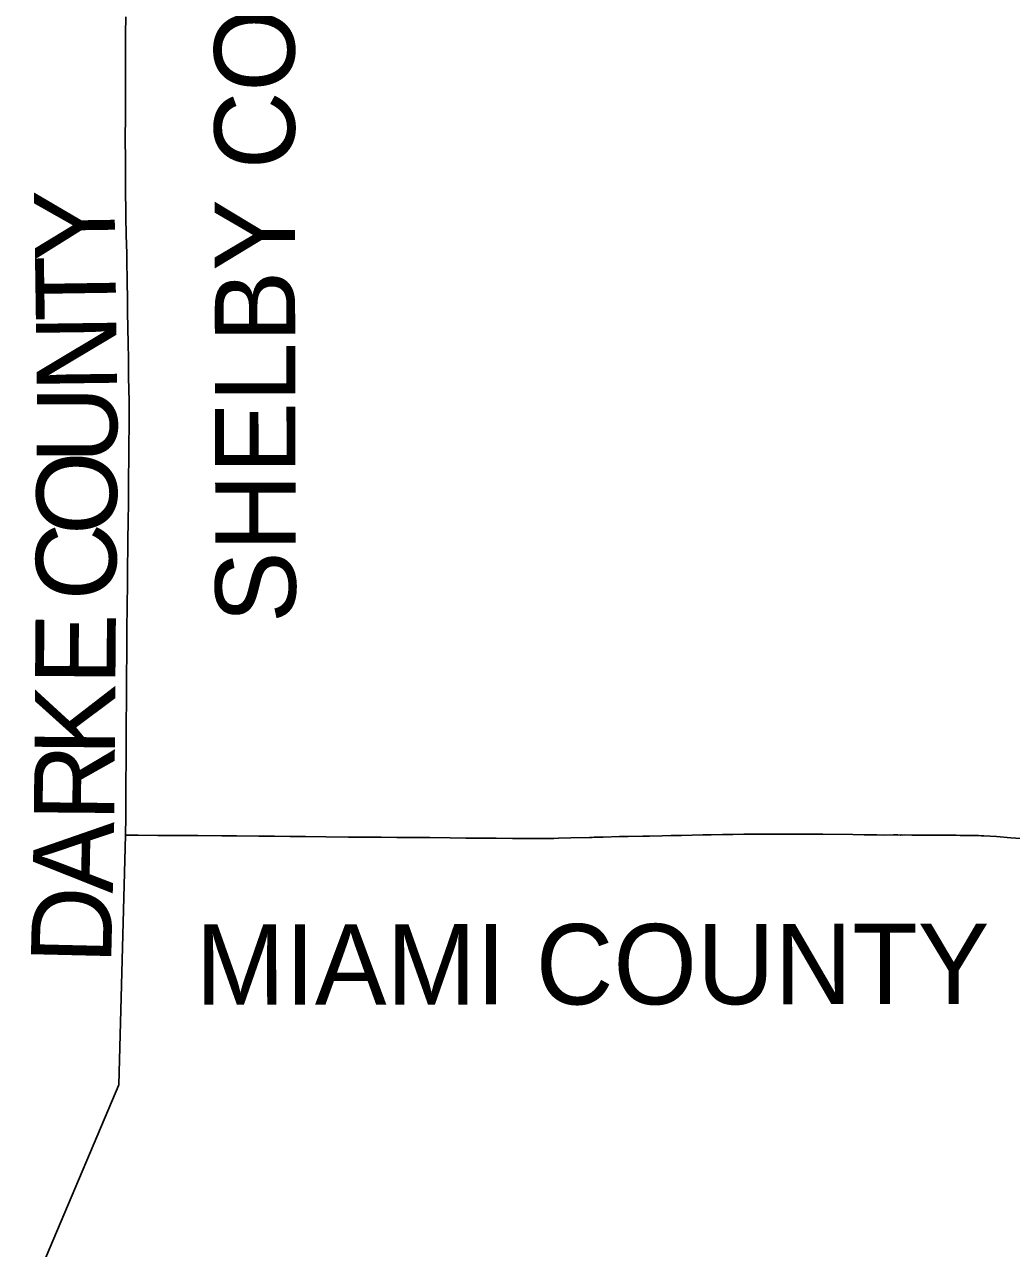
# Model space of a CAD drawing. Extents: x 0 to 34, y 0 to 22.
# Drawn here: x 4.2472 to 4.4446, y 17.6689 to 17.9138 of the extents above; entities that cross this region are included whole.
import ezdxf

# ---------------------------------------------------------------- set-up
doc = ezdxf.new("R2010")
doc.units = 0
doc.layers.add('GM_X_County', color=7, linetype='Continuous')
doc.layers.add('GM_X_County_Text', color=7, linetype='Continuous')

msp = doc.modelspace()

# ---------------------------------------------------------------- linework, layer by layer
at = {"layer": 'GM_X_County'}
for points in [[(4.267452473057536, 17.915329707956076), (4.267428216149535, 17.91190238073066), (4.267434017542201, 17.907208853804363), (4.267425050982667, 17.90367499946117), (4.2674208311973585, 17.90019493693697), (4.267419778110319, 17.898137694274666), (4.2673939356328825, 17.8954486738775), (4.267370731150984, 17.890966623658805), (4.267396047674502, 17.88664225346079), (4.267389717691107, 17.883953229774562), (4.267434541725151, 17.87925970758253), (4.267442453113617, 17.87751994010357), (4.267506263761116, 17.87435682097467), (4.267535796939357, 17.87256431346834), (4.267556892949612, 17.871510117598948), (4.267595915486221, 17.869982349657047), (4.267660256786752, 17.86776690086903), (4.267675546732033, 17.86660670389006), (4.26768715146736, 17.865190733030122), (4.267716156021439, 17.86372361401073), (4.267744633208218, 17.86187784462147), (4.267779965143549, 17.859293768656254), (4.267803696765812, 17.857817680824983), (4.267830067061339, 17.856446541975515), (4.267866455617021, 17.852914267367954), (4.267929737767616, 17.850173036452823), (4.2679930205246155, 17.846692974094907), (4.268041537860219, 17.84316017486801), (4.268120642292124, 17.838414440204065), (4.268126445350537, 17.837349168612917), (4.268130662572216, 17.83651488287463), (4.268118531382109, 17.83456364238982), (4.26811326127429, 17.833034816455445), (4.268107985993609, 17.830239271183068), (4.268076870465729, 17.826547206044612), (4.26803257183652, 17.823489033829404), (4.267976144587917, 17.81853182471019), (4.267916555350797, 17.813891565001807), (4.2678843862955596, 17.811149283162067), (4.267845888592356, 17.808670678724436), (4.267789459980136, 17.805613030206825), (4.2677773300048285, 17.801869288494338), (4.267734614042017, 17.797439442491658), (4.2676987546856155, 17.79264044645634), (4.26765867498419, 17.788211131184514), (4.267622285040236, 17.783253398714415), (4.267595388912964, 17.780775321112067), (4.267544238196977, 17.771757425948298), (4.267514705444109, 17.767749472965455), (4.267482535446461, 17.76089428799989), (4.267474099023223, 17.758204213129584), (4.2674530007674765, 17.755251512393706), (4.267427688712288, 17.75160902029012), (4.266090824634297, 17.701618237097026), (4.247204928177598, 17.65706455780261)], [(4.449619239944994, 17.750726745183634), (4.444516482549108, 17.7510885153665), (4.4416254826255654, 17.751307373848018), (4.439100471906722, 17.75146241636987), (4.438539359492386, 17.75148298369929), (4.438047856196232, 17.751500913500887), (4.436942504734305, 17.751507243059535), (4.436678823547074, 17.75151567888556), (4.436098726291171, 17.751522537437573), (4.434357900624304, 17.751543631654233), (4.433567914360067, 17.751566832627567), (4.432671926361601, 17.75156946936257), (4.431828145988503, 17.751581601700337), (4.431038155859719, 17.751600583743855), (4.427400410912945, 17.751621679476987), (4.4267681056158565, 17.751616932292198), (4.425660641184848, 17.751622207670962), (4.424711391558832, 17.751623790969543), (4.423183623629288, 17.751635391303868), (4.422869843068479, 17.751618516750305), (4.422553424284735, 17.75162642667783), (4.422343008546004, 17.751616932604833), (4.421869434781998, 17.75164171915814), (4.421027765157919, 17.75164910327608), (4.419024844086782, 17.751619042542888), (4.417704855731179, 17.75162589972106), (4.415175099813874, 17.75167599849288), (4.412855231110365, 17.75169340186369), (4.406897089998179, 17.751783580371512), (4.401361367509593, 17.75180625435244), (4.399832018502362, 17.751788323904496), (4.397563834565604, 17.751815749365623), (4.395139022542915, 17.75181785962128), (4.392397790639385, 17.7517888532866), (4.391079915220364, 17.75176881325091), (4.388865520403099, 17.751733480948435), (4.3868082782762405, 17.75170341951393), (4.384541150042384, 17.75168179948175), (4.382854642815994, 17.75165226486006), (4.378637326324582, 17.751554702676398), (4.37652735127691, 17.751521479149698), (4.374735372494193, 17.751489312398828), (4.37220456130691, 17.751422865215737), (4.370886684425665, 17.75140756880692), (4.367935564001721, 17.751330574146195), (4.366194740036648, 17.751295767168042), (4.362927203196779, 17.75122299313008), (4.361717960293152, 17.75117658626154), (4.361562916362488, 17.75115970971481), (4.361143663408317, 17.751161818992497), (4.360724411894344, 17.751144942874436), (4.3606205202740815, 17.751135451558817), (4.3602002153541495, 17.75114599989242), (4.356511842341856, 17.75105529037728), (4.354035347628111, 17.75098989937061), (4.353086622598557, 17.750954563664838), (4.352861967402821, 17.750950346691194), (4.352083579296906, 17.75093610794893), (4.350342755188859, 17.75093716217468), (4.349129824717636, 17.75093452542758), (4.344804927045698, 17.750954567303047), (4.341536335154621, 17.75099148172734), (4.3383194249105, 17.75100255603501), (4.335472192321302, 17.751018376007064), (4.332360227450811, 17.751040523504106), (4.328247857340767, 17.751092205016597), (4.3235543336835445, 17.751110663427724), (4.3217080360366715, 17.751130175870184), (4.318544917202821, 17.751191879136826), (4.3154345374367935, 17.751212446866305), (4.312006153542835, 17.75122457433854), (4.307471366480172, 17.75126518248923), (4.303411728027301, 17.75130842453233), (4.300351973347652, 17.751312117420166), (4.297188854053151, 17.751360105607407), (4.294077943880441, 17.751386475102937), (4.289595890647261, 17.751434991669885), (4.286695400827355, 17.751448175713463), (4.281844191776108, 17.751508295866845), (4.279417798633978, 17.751534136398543), (4.2781004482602, 17.751553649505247), (4.273882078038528, 17.751552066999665), (4.269926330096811, 17.75158159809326), (4.267427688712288, 17.75160902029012), (4.2674530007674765, 17.755251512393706), (4.267474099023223, 17.758204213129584), (4.267482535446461, 17.76089428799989), (4.267514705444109, 17.767749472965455), (4.267544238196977, 17.771757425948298), (4.267595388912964, 17.780775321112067), (4.267622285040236, 17.783253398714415), (4.26765867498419, 17.788211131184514), (4.2676987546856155, 17.79264044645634), (4.267734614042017, 17.797439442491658), (4.2677773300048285, 17.801869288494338), (4.267789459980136, 17.805613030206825), (4.267845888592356, 17.808670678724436), (4.2678843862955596, 17.811149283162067), (4.267916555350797, 17.813891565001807), (4.267976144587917, 17.81853182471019), (4.26803257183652, 17.823489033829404), (4.268076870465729, 17.826547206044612), (4.268107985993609, 17.830239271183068), (4.26811326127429, 17.833034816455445), (4.268118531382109, 17.83456364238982), (4.268130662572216, 17.83651488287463), (4.268126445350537, 17.837349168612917), (4.268120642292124, 17.838414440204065), (4.268041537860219, 17.84316017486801), (4.2679930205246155, 17.846692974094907), (4.267929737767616, 17.850173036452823), (4.267866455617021, 17.852914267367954), (4.267830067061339, 17.856446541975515), (4.267803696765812, 17.857817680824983), (4.267779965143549, 17.859293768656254), (4.267744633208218, 17.86187784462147), (4.267716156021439, 17.86372361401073), (4.26768715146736, 17.865190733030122), (4.267675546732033, 17.86660670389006), (4.267660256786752, 17.86776690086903), (4.267595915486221, 17.869982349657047), (4.267556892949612, 17.871510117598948), (4.267535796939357, 17.87256431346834), (4.267506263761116, 17.87435682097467), (4.267442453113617, 17.87751994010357), (4.267434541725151, 17.87925970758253), (4.267389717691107, 17.883953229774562), (4.267396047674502, 17.88664225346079), (4.267370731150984, 17.890966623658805), (4.2673939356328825, 17.8954486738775), (4.267419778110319, 17.898137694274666), (4.2674208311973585, 17.90019493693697), (4.267425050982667, 17.90367499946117), (4.267434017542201, 17.907208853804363), (4.267428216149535, 17.91190238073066), (4.267452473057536, 17.915329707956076)], [(4.247204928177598, 17.65706455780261), (4.266090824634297, 17.701618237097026), (4.267427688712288, 17.75160902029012), (4.269926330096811, 17.75158159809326), (4.273882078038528, 17.751552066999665), (4.2781004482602, 17.751553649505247), (4.279417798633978, 17.751534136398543), (4.281844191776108, 17.751508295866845), (4.286695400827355, 17.751448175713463), (4.289595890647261, 17.751434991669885), (4.294077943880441, 17.751386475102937), (4.297188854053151, 17.751360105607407), (4.300351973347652, 17.751312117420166), (4.303411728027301, 17.75130842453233), (4.307471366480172, 17.75126518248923), (4.312006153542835, 17.75122457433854), (4.3154345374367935, 17.751212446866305), (4.318544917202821, 17.751191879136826), (4.3217080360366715, 17.751130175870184), (4.3235543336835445, 17.751110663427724), (4.328247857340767, 17.751092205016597), (4.332360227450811, 17.751040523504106), (4.335472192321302, 17.751018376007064), (4.3383194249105, 17.75100255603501), (4.341536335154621, 17.75099148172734), (4.344804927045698, 17.750954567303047), (4.349129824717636, 17.75093452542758), (4.350342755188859, 17.75093716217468), (4.352083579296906, 17.75093610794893), (4.352861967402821, 17.750950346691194), (4.353086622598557, 17.750954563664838), (4.354035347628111, 17.75098989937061), (4.356511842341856, 17.75105529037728), (4.3602002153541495, 17.75114599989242), (4.3606205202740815, 17.751135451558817), (4.360724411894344, 17.751144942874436), (4.361143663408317, 17.751161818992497), (4.361562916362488, 17.75115970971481), (4.361717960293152, 17.75117658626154), (4.362927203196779, 17.75122299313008), (4.366194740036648, 17.751295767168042), (4.367935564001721, 17.751330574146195), (4.370886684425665, 17.75140756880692), (4.37220456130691, 17.751422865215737), (4.374735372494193, 17.751489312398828), (4.37652735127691, 17.751521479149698), (4.378637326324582, 17.751554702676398), (4.382854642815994, 17.75165226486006), (4.384541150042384, 17.75168179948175), (4.3868082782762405, 17.75170341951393), (4.388865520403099, 17.751733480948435), (4.391079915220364, 17.75176881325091), (4.392397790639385, 17.7517888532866), (4.395139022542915, 17.75181785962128), (4.397563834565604, 17.751815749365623), (4.399832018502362, 17.751788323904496), (4.401361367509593, 17.75180625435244), (4.406897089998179, 17.751783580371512), (4.412855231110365, 17.75169340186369), (4.415175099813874, 17.75167599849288), (4.417704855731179, 17.75162589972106), (4.419024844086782, 17.751619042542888), (4.421027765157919, 17.75164910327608), (4.421869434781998, 17.75164171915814), (4.422343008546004, 17.751616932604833), (4.422553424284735, 17.75162642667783), (4.422869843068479, 17.751618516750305), (4.423183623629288, 17.751635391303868), (4.424711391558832, 17.751623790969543), (4.425660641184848, 17.751622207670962), (4.4267681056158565, 17.751616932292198), (4.427400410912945, 17.751621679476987), (4.431038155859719, 17.751600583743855), (4.431828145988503, 17.751581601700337), (4.432671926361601, 17.75156946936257), (4.433567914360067, 17.751566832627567), (4.434357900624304, 17.751543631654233), (4.436098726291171, 17.751522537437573), (4.436678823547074, 17.75151567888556), (4.436942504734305, 17.751507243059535), (4.438047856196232, 17.751500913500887), (4.438539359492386, 17.75148298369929), (4.439100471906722, 17.75146241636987), (4.4416254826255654, 17.751307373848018), (4.444516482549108, 17.7510885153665), (4.449619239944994, 17.750726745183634)]]:
    msp.add_lwpolyline(points, dxfattribs=at)

# ---------------------------------------------------------------- texts
at = {"layer": 'GM_X_County_Text'}
for s, height, rotation, p in [('SHELBY COUNTY', 0.016074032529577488, 90.122917, (4.301477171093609, 17.794024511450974)), ('Y', 0.016074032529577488, 90.854012, (4.265387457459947, 17.866547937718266)), ('T', 0.016074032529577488, 90.854012, (4.265566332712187, 17.854548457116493)), ('N', 0.016074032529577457, 90.781677, (4.265760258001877, 17.840339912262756)), ('U', 0.016074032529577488, 89.885521, (4.2657335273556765, 17.82587763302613)), ('O', 0.016074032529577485, 89.54287, (4.265619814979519, 17.811585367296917)), ('C', 0.016074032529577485, 89.542633, (4.26551526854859, 17.798482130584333)), ('E', 0.016074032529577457, 89.542061, (4.265380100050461, 17.781570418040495)), ('K', 0.016074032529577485, 89.54287, (4.265266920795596, 17.76738321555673)), ('R', 0.016074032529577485, 89.481171, (4.26514803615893, 17.754261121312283)), ('A', 0.01607403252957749, 88.867828, (4.264865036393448, 17.73988807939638)), ('D', 0.016074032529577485, 88.643387, (4.264527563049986, 17.72563534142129)), ('MIAMI COUNTY', 0.016074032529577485, 0.05373900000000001, (4.281408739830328, 17.71766489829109))]:
    msp.add_text(s, height=height, rotation=rotation, dxfattribs=at).set_placement(p)

doc.saveas('drawing.dxf')
